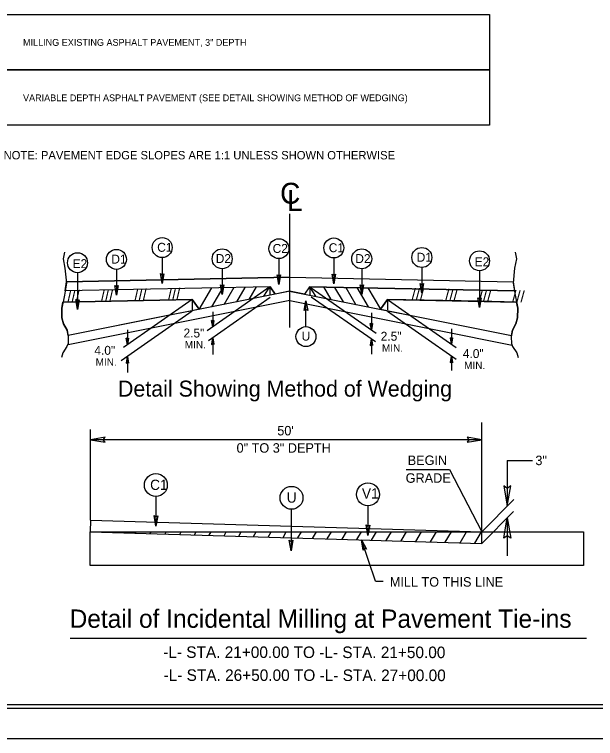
# Model space of a CAD drawing. Extents: x 1497225 to 1499181, y 579958 to 582278.
# Drawn here: x 1497449 to 1497879, y 581178 to 581713 of the extents above; entities that cross this region are included whole.
import ezdxf

# ---------------------------------------------------------------- set-up
doc = ezdxf.new("R2010")
doc.units = 0
for name, color, linetype in [('Default', 7, 'Continuous'), ('Old_Level_1', 7, 'Continuous'), ('Old_Level_11', 7, 'Continuous'), ('Old_Level_4', 7, 'Continuous'), ('Prop Dimension', 7, 'Continuous'), ('Prop Dimension Text', 7, 'Continuous'), ('Prop EOT', 7, 'Continuous'), ('Prop Pavement Schedule Description CELL', 7, 'Continuous'), ('Sheet Cutting Line CELL', 7, 'Continuous'), ('Sheet Plot Border Inside CELL', 7, 'Continuous'), ('Sheet Plot Border Outside CELL', 7, 'Continuous'), ('Sheet Typical CELL', 7, 'Continuous'), ('Typical Detail Wedge2 CELL', 7, 'Continuous'), ('Typical ID Circle CELL', 7, 'Continuous'), ('Typical Terminator CELL', 7, 'Continuous'), ('Typical Text Centerline CELL', 7, 'Continuous'), ('Typical Text General CELL', 7, 'Continuous'), ('Typical Text ID Circle CELL', 7, 'Continuous')]:
    doc.layers.add(name, color=color, linetype=linetype)

msp = doc.modelspace()

# ---------------------------------------------------------------- linework, layer by layer
at = {"layer": 'Default'}
for p, q in [((1497813.43, 581383.14), (1497813.43, 581349.46)), ((1497813.43, 581383.14), (1497832.03, 581383.14)), ((1497818.38, 581354.4), (1497794.6, 581330.63)), ((1497818.12, 581345.54), (1497794.6, 581322.03)), ((1497813.43, 581340.86), (1497813.43, 581312.76))]:
    msp.add_line(p, q, dxfattribs=at)
at = {"layer": 'Old_Level_1'}
for p, q in [((1497738.7, 581376.51), (1497770.88, 581376.51)), ((1497770.88, 581376.51), (1497794.6, 581330.63)), ((1497715.98, 581294.03), (1497705.67, 581324.67)), ((1497715.98, 581294.03), (1497721.85, 581294.03)), ((1497490.52, 581252), (1497871.88, 581252))]:
    msp.add_line(p, q, dxfattribs=at)
at = {"layer": 'Old_Level_11'}
for points in [[(1497516.3, 581400.45), (1497505.57, 581398.59), (1497516.37, 581396.67), (1497515, 581398.57)], [(1497783.88, 581396.71), (1497794.6, 581398.59), (1497783.79, 581400.48), (1497785.17, 581398.59)]]:
    msp.add_lwpolyline(points, close=True, dxfattribs=at)
at = {"layer": 'Prop Dimension'}
for p, q in [((1497794.6, 581330.63), (1497794.6, 581411.36)), ((1497505.57, 581339.22), (1497505.57, 581406.18)), ((1497794.6, 581398.59), (1497505.57, 581398.59))]:
    msp.add_line(p, q, dxfattribs=at)
msp.add_lwpolyline([(1497505.31, 581330.63), (1497869.71, 581330.63), (1497869.71, 581305.58), (1497505.31, 581305.58)], close=True, dxfattribs=at)
at = {"layer": 'Prop EOT'}
for p, q in [((1497505.57, 581339.22), (1497505.31, 581330.63)), ((1497505.57, 581339.22), (1497794.6, 581330.63)), ((1497505.31, 581330.63), (1497794.6, 581322.03)), ((1497506.1, 581330.6), (1497506.12, 581330.63)), ((1497517, 581330.28), (1497517.2, 581330.63)), ((1497527.9, 581329.96), (1497528.29, 581330.63)), ((1497538.8, 581329.63), (1497539.37, 581330.63)), ((1497549.69, 581329.31), (1497550.46, 581330.63)), ((1497560.59, 581328.98), (1497561.54, 581330.63)), ((1497571.49, 581328.66), (1497572.63, 581330.63)), ((1497582.39, 581328.34), (1497583.71, 581330.63)), ((1497593.29, 581328.01), (1497594.8, 581330.63)), ((1497604.18, 581327.69), (1497605.88, 581330.63)), ((1497615.08, 581327.37), (1497616.97, 581330.63)), ((1497625.98, 581327.04), (1497628.05, 581330.63)), ((1497636.88, 581326.72), (1497639.14, 581330.63)), ((1497647.78, 581326.39), (1497650.22, 581330.63)), ((1497658.68, 581326.07), (1497661.31, 581330.63)), ((1497669.57, 581325.75), (1497672.39, 581330.63)), ((1497680.47, 581325.42), (1497683.48, 581330.63)), ((1497691.37, 581325.1), (1497694.56, 581330.63)), ((1497702.27, 581324.77), (1497705.65, 581330.63)), ((1497713.17, 581324.45), (1497716.73, 581330.63)), ((1497724.06, 581324.13), (1497727.82, 581330.63)), ((1497734.96, 581323.8), (1497738.9, 581330.63)), ((1497745.86, 581323.48), (1497749.99, 581330.63)), ((1497756.76, 581323.15), (1497761.07, 581330.63)), ((1497767.66, 581322.83), (1497772.16, 581330.63)), ((1497778.55, 581322.51), (1497783.24, 581330.63)), ((1497789.45, 581322.18), (1497794.33, 581330.63)), ((1497794.6, 581322.03), (1497794.6, 581330.63))]:
    msp.add_line(p, q, dxfattribs=at)
at = {"layer": 'Prop Pavement Schedule Description CELL'}
for points in [[(1497441.11, 581671.59), (1497400.21, 581671.59), (1497400.21, 581712.5), (1497800.21, 581712.5), (1497800.21, 581671.59), (1497441.11, 581671.59), (1497441.11, 581712.5)], [(1497441.11, 581630.68), (1497400.21, 581630.68), (1497400.21, 581671.59), (1497800.21, 581671.59), (1497800.21, 581630.68), (1497441.11, 581630.68), (1497441.11, 581671.59)]]:
    msp.add_lwpolyline(points, dxfattribs=at)
at = {"layer": 'Sheet Cutting Line CELL'}
msp.add_line((1497225.23, 581177.96), (1498909.23, 581177.96), dxfattribs=at)
at = {"layer": 'Sheet Plot Border Inside CELL'}
msp.add_lwpolyline([(1498904.73, 582255.51), (1497238.23, 582255.51), (1497238.23, 581200.41), (1498904.73, 581200.41)], close=True, dxfattribs=at)
at = {"layer": 'Sheet Plot Border Outside CELL'}
msp.add_lwpolyline([(1498909.23, 582277.96), (1497225.23, 582277.96), (1497225.23, 581177.96), (1498909.23, 581177.96)], close=True, dxfattribs=at)
at = {"layer": 'Sheet Typical CELL'}
msp.add_lwpolyline([(1498892.23, 582252.96), (1497392.23, 582252.96), (1497392.23, 581202.96), (1498892.23, 581202.96)], close=True, dxfattribs=at)
at = {"layer": 'Typical Detail Wedge2 CELL'}
for p, q in [((1497652.78, 581481.31), (1497652.78, 581565.38)), ((1497652.78, 581481.31), (1497652.78, 581538.73)), ((1497486.83, 581508.52), (1497487.77, 581515.15)), ((1497652.77, 581518.45), (1497487.77, 581515.15)), ((1497487.77, 581515.15), (1497652.77, 581518.45)), ((1497652.77, 581518.45), (1497817.78, 581515.15)), ((1497652.79, 581518.45), (1497817.78, 581515.15)), ((1497817.78, 581515.15), (1497818.73, 581508.52)), ((1497638.3, 581511.55), (1497486.83, 581508.52)), ((1497638.3, 581511.55), (1497486.83, 581508.52)), ((1497595.03, 581510.68), (1497585.65, 581494.62)), ((1497638.11, 581511.43), (1497591.62, 581478.87)), ((1497603.26, 581510.85), (1497594.96, 581496.61)), ((1497611.41, 581511.01), (1497603.96, 581498.24)), ((1497619.62, 581510.99), (1497613.45, 581500.42)), ((1497627.9, 581511.42), (1497622.52, 581502.19)), ((1497633.61, 581504.5), (1497638.09, 581511.49)), ((1497638.09, 581511.49), (1497638.09, 581505.74)), ((1497642.01, 581506.12), (1497638.3, 581511.55)), ((1497638.3, 581511.38), (1497642.01, 581506.12)), ((1497667.37, 581511.55), (1497663.55, 581506.12)), ((1497667.37, 581511.55), (1497663.55, 581506.12)), ((1497667.13, 581511.43), (1497667.37, 581511.42)), ((1497667.37, 581511.55), (1497818.73, 581508.52)), ((1497818.73, 581508.52), (1497667.37, 581511.55)), ((1497671.95, 581504.5), (1497667.47, 581511.49)), ((1497667.47, 581511.49), (1497667.47, 581505.16)), ((1497668.63, 581510.67), (1497716.53, 581477.13)), ((1497677.65, 581511.42), (1497683.04, 581502.19)), ((1497685.93, 581510.99), (1497692.1, 581500.42)), ((1497694.14, 581511.01), (1497701.6, 581498.24)), ((1497702.29, 581510.85), (1497710.6, 581496.61)), ((1497710.54, 581510.68), (1497719.77, 581494.85)), ((1497653.02, 581508.31), (1497489.01, 581475.5)), ((1497638.22, 581503.47), (1497592.73, 581471.62)), ((1497652.53, 581508.31), (1497642.01, 581506.12)), ((1497652.53, 581508.31), (1497816.55, 581475.5)), ((1497663.55, 581506.12), (1497652.53, 581508.31)), ((1497668.57, 581504.15), (1497716, 581470.95)), ((1497580.59, 581502.13), (1497485.23, 581500.21)), ((1497485.23, 581500.21), (1497580.59, 581502.13)), ((1497652.71, 581501.25), (1497488.96, 581468.49)), ((1497580.59, 581502.13), (1497529.96, 581466.66)), ((1497585.78, 581494.83), (1497580.59, 581502.13)), ((1497580.59, 581502.13), (1497580.59, 581493.8)), ((1497580.59, 581502.13), (1497585.77, 581494.85)), ((1497652.84, 581501.25), (1497816.98, 581468.41)), ((1497724.96, 581502.13), (1497719.77, 581494.85)), ((1497719.78, 581494.85), (1497724.96, 581502.13)), ((1497724.96, 581502.13), (1497820.33, 581500.21)), ((1497724.96, 581502.13), (1497724.96, 581494.39)), ((1497792.97, 581500.76), (1497724.96, 581502.13)), ((1497725.73, 581501.59), (1497775.67, 581466.61)), ((1497820.33, 581500.21), (1497792.97, 581500.76)), ((1497580.55, 581493.54), (1497528.2, 581456.7)), ((1497580.59, 581493.81), (1497563.99, 581490.49)), ((1497585.77, 581494.85), (1497580.59, 581493.81)), ((1497595.86, 581492.9), (1497595.86, 581481.84)), ((1497719.77, 581494.85), (1497741.57, 581490.49)), ((1497724.96, 581493.38), (1497775.59, 581457.92)), ((1497563.99, 581490.49), (1497489.01, 581475.5)), ((1497713.03, 581492.26), (1497713.03, 581479.58)), ((1497741.57, 581490.49), (1497816.55, 581475.5)), ((1497595.86, 581481.84), (1497595, 581486.69)), ((1497595.86, 581486.06), (1497595, 581486.69)), ((1497595.86, 581481.84), (1497595.12, 581486.6)), ((1497595.24, 581486.51), (1497595.86, 581481.84)), ((1497595.86, 581481.84), (1497595.36, 581486.42)), ((1497595.49, 581486.33), (1497595.86, 581481.84)), ((1497595.86, 581481.84), (1497595.61, 581486.24)), ((1497595.73, 581486.15), (1497595.86, 581481.84)), ((1497595.86, 581481.84), (1497596.72, 581486.69)), ((1497596.72, 581486.69), (1497595.86, 581486.06)), ((1497596.6, 581486.6), (1497595.86, 581481.84)), ((1497595.86, 581481.84), (1497596.46, 581486.51)), ((1497596.34, 581486.42), (1497595.86, 581481.84)), ((1497595.86, 581481.84), (1497596.22, 581486.33)), ((1497596.1, 581486.24), (1497595.86, 581481.84)), ((1497595.86, 581481.84), (1497595.98, 581486.15)), ((1497595.86, 581486.06), (1497595.86, 581481.84)), ((1497713.03, 581479.58), (1497712.18, 581484.44)), ((1497713.03, 581483.81), (1497712.18, 581484.44)), ((1497713.03, 581479.58), (1497712.3, 581484.35)), ((1497712.42, 581484.26), (1497713.03, 581479.58)), ((1497713.03, 581479.58), (1497712.54, 581484.16)), ((1497712.66, 581484.07), (1497713.03, 581479.58)), ((1497713.03, 581479.58), (1497712.78, 581483.99)), ((1497712.9, 581483.9), (1497713.03, 581479.58)), ((1497713.03, 581479.58), (1497713.89, 581484.44)), ((1497713.89, 581484.44), (1497713.03, 581483.81)), ((1497713.76, 581484.35), (1497713.03, 581479.58)), ((1497713.03, 581479.58), (1497713.64, 581484.26)), ((1497713.52, 581484.16), (1497713.03, 581479.58)), ((1497713.03, 581479.58), (1497713.4, 581484.07)), ((1497713.27, 581483.99), (1497713.03, 581479.58)), ((1497713.03, 581479.58), (1497713.15, 581483.9)), ((1497713.03, 581483.81), (1497713.03, 581479.58)), ((1497532.81, 581479.68), (1497532.81, 581468.65)), ((1497772.24, 581480.48), (1497772.24, 581469.02)), ((1497532.81, 581468.65), (1497531.95, 581473.51)), ((1497532.81, 581472.88), (1497531.95, 581473.51)), ((1497532.81, 581468.65), (1497532.07, 581473.42)), ((1497532.2, 581473.32), (1497532.81, 581468.65)), ((1497532.81, 581468.65), (1497532.32, 581473.24)), ((1497532.44, 581473.15), (1497532.81, 581468.65)), ((1497532.81, 581468.65), (1497532.56, 581473.06)), ((1497532.69, 581472.97), (1497532.81, 581468.65)), ((1497532.81, 581468.65), (1497533.66, 581473.51)), ((1497533.66, 581473.51), (1497532.81, 581472.88)), ((1497533.54, 581473.42), (1497532.81, 581468.65)), ((1497532.81, 581468.65), (1497533.42, 581473.32)), ((1497533.3, 581473.24), (1497532.81, 581468.65)), ((1497532.81, 581468.65), (1497533.17, 581473.15)), ((1497533.06, 581473.06), (1497532.81, 581468.65)), ((1497532.81, 581468.65), (1497532.93, 581472.97)), ((1497532.81, 581472.88), (1497532.81, 581468.65)), ((1497595.86, 581473.81), (1497595, 581468.96)), ((1497595.12, 581469.05), (1497595.86, 581473.81)), ((1497595.86, 581473.81), (1497595.24, 581469.14)), ((1497595.36, 581469.24), (1497595.86, 581473.81)), ((1497595.86, 581473.81), (1497595.49, 581469.32)), ((1497595.61, 581469.41), (1497595.86, 581473.81)), ((1497595.86, 581473.81), (1497595.73, 581469.5)), ((1497595.86, 581473.81), (1497595.86, 581461.36)), ((1497595.86, 581473.81), (1497596.72, 581468.96)), ((1497595.86, 581469.59), (1497595.86, 581473.81)), ((1497595.98, 581469.5), (1497595.86, 581473.81)), ((1497595.86, 581473.81), (1497596.1, 581469.41)), ((1497596.22, 581469.32), (1497595.86, 581473.81)), ((1497595.86, 581473.81), (1497596.34, 581469.24)), ((1497596.46, 581469.14), (1497595.86, 581473.81)), ((1497595.86, 581473.81), (1497596.6, 581469.05)), ((1497713.03, 581473.02), (1497712.18, 581468.17)), ((1497712.3, 581468.27), (1497713.03, 581473.02)), ((1497713.03, 581473.02), (1497712.42, 581468.35)), ((1497712.54, 581468.45), (1497713.03, 581473.02)), ((1497713.03, 581473.02), (1497712.66, 581468.53)), ((1497712.78, 581468.62), (1497713.03, 581473.02)), ((1497713.03, 581473.02), (1497712.9, 581468.71)), ((1497713.03, 581473.02), (1497713.03, 581461.68)), ((1497713.03, 581473.02), (1497713.89, 581468.17)), ((1497713.03, 581468.8), (1497713.03, 581473.02)), ((1497713.15, 581468.71), (1497713.03, 581473.02)), ((1497713.03, 581473.02), (1497713.27, 581468.62)), ((1497713.4, 581468.53), (1497713.03, 581473.02)), ((1497713.03, 581473.02), (1497713.52, 581468.45)), ((1497713.64, 581468.35), (1497713.03, 581473.02)), ((1497713.03, 581473.02), (1497713.76, 581468.27)), ((1497772.24, 581469.02), (1497771.39, 581473.86)), ((1497772.24, 581473.24), (1497771.39, 581473.86)), ((1497772.24, 581469.02), (1497771.51, 581473.77)), ((1497771.63, 581473.69), (1497772.24, 581469.02)), ((1497772.24, 581469.02), (1497771.75, 581473.6)), ((1497771.87, 581473.51), (1497772.24, 581469.02)), ((1497772.24, 581469.02), (1497771.99, 581473.42)), ((1497772.11, 581473.32), (1497772.24, 581469.02)), ((1497772.24, 581469.02), (1497773.1, 581473.86)), ((1497773.1, 581473.86), (1497772.24, 581473.24)), ((1497772.97, 581473.77), (1497772.24, 581469.02)), ((1497772.24, 581469.02), (1497772.85, 581473.69)), ((1497772.73, 581473.6), (1497772.24, 581469.02)), ((1497772.24, 581469.02), (1497772.6, 581473.51)), ((1497772.48, 581473.42), (1497772.24, 581469.02)), ((1497772.24, 581469.02), (1497772.36, 581473.32)), ((1497772.24, 581473.24), (1497772.24, 581469.02)), ((1497595, 581468.96), (1497595.86, 581469.59)), ((1497595.86, 581469.59), (1497596.72, 581468.96)), ((1497712.18, 581468.17), (1497713.03, 581468.8)), ((1497713.03, 581468.8), (1497713.89, 581468.17)), ((1497772.24, 581460.27), (1497771.39, 581455.42)), ((1497771.51, 581455.51), (1497772.24, 581460.27)), ((1497772.24, 581460.27), (1497771.63, 581455.6)), ((1497771.75, 581455.69), (1497772.24, 581460.27)), ((1497772.24, 581460.27), (1497771.87, 581455.78)), ((1497771.99, 581455.87), (1497772.24, 581460.27)), ((1497772.24, 581460.27), (1497772.11, 581455.96)), ((1497772.24, 581460.27), (1497772.24, 581449.62)), ((1497772.24, 581460.27), (1497773.1, 581455.42)), ((1497772.24, 581456.05), (1497772.24, 581460.27)), ((1497772.36, 581455.96), (1497772.24, 581460.27)), ((1497772.24, 581460.27), (1497772.48, 581455.87)), ((1497772.6, 581455.78), (1497772.24, 581460.27)), ((1497772.24, 581460.27), (1497772.73, 581455.69)), ((1497772.85, 581455.6), (1497772.24, 581460.27)), ((1497772.24, 581460.27), (1497772.97, 581455.51)), ((1497532.81, 581459.93), (1497531.95, 581455.08)), ((1497531.95, 581455.08), (1497532.81, 581455.71)), ((1497532.08, 581455.17), (1497532.81, 581459.93)), ((1497532.81, 581459.93), (1497532.2, 581455.26)), ((1497532.32, 581455.35), (1497532.81, 581459.93)), ((1497532.81, 581459.93), (1497532.44, 581455.44)), ((1497532.56, 581455.53), (1497532.81, 581459.93)), ((1497532.81, 581459.93), (1497532.69, 581455.61)), ((1497532.81, 581459.93), (1497532.81, 581448.14)), ((1497532.81, 581459.93), (1497533.66, 581455.08)), ((1497532.81, 581455.71), (1497532.81, 581459.93)), ((1497532.93, 581455.61), (1497532.81, 581459.93)), ((1497532.81, 581459.93), (1497533.06, 581455.53)), ((1497533.18, 581455.44), (1497532.81, 581459.93)), ((1497532.81, 581459.93), (1497533.3, 581455.35)), ((1497533.42, 581455.26), (1497532.81, 581459.93)), ((1497532.81, 581459.93), (1497533.54, 581455.17)), ((1497532.81, 581455.71), (1497533.66, 581455.08)), ((1497771.39, 581455.42), (1497772.24, 581456.05)), ((1497772.24, 581456.05), (1497773.1, 581455.42))]:
    msp.add_line(p, q, dxfattribs=at)
for points in [[(1497486.24, 581536.93), (1497485.36, 581532.1), (1497486.68, 581525.22), (1497487.85, 581514.1), (1497486.24, 581505.32), (1497484.34, 581495.8), (1497484.49, 581488.63), (1497485.66, 581484.1), (1497488.3, 581479.55), (1497489.17, 581474.58), (1497489.02, 581469.61), (1497488.14, 581467.26), (1497485.07, 581462.58), (1497484.05, 581459.35)], [(1497819.31, 581536.93), (1497820.19, 581532.1), (1497818.88, 581525.22), (1497817.7, 581514.1), (1497819.31, 581505.32), (1497821.22, 581495.8), (1497821.07, 581488.63), (1497819.89, 581484.1), (1497817.26, 581479.55), (1497816.39, 581474.58), (1497816.53, 581469.61), (1497817.41, 581467.26), (1497820.48, 581462.58), (1497821.5, 581459.35)], [(1497489.01, 581475.5), (1497488.3, 581479.55), (1497485.66, 581484.1), (1497484.49, 581488.63), (1497484.34, 581495.8), (1497485.22, 581500.21)], [(1497816.55, 581475.5), (1497817.26, 581479.55), (1497819.89, 581484.1), (1497821.07, 581488.63), (1497821.22, 581495.8), (1497820.33, 581500.21)]]:
    msp.add_lwpolyline(points, dxfattribs=at)
at = {"layer": 'Typical ID Circle CELL'}
for p, q in [((1497558.51, 581533.05), (1497558.51, 581514)), ((1497644.76, 581532.23), (1497644.76, 581513.18)), ((1497685.28, 581532.75), (1497685.28, 581513.7)), ((1497602.82, 581524.77), (1497602.82, 581505.72)), ((1497705.92, 581524.73), (1497705.92, 581505.68)), ((1497750.32, 581525.72), (1497750.32, 581506.67)), ((1497495.93, 581521.87), (1497495.93, 581494.79)), ((1497524.71, 581524.34), (1497524.71, 581505.3)), ((1497792.97, 581523.29), (1497792.97, 581496.21)), ((1497664.72, 581482.03), (1497664.72, 581501.08)), ((1497553.85, 581356.59), (1497553.85, 581334.72)), ((1497710.51, 581349.7), (1497710.51, 581327.83)), ((1497653.79, 581347.2), (1497653.79, 581316.64))]:
    msp.add_line(p, q, dxfattribs=at)
for centre, radius in [((1497558.51, 581540.41), 7.37), ((1497644.76, 581539.6), 7.37), ((1497685.28, 581540.12), 7.37), ((1497750.32, 581533.08), 7.37), ((1497495.93, 581529.24), 7.37), ((1497524.71, 581531.71), 7.37), ((1497602.82, 581532.13), 7.37), ((1497705.92, 581532.1), 7.37), ((1497792.97, 581530.66), 7.37), ((1497664.72, 581474.67), 7.37), ((1497553.85, 581365.05), 8.46), ((1497654.06, 581355.66), 8.46), ((1497710.51, 581358.16), 8.46)]:
    msp.add_circle(centre, radius, dxfattribs=at)
at = {"layer": 'Typical Terminator CELL'}
for points in [[(1497559.74, 581521.14), (1497558.51, 581514), (1497557.24, 581521.18), (1497558.51, 581520.27)], [(1497559.74, 581521.14), (1497558.51, 581514), (1497557.24, 581521.18), (1497558.51, 581520.27)], [(1497645.99, 581520.33), (1497644.76, 581513.18), (1497643.49, 581520.37), (1497644.76, 581519.46)], [(1497645.99, 581520.33), (1497644.76, 581513.18), (1497643.49, 581520.37), (1497644.76, 581519.46)], [(1497686.51, 581520.85), (1497685.28, 581513.7), (1497684.01, 581520.89), (1497685.28, 581519.98)], [(1497686.51, 581520.85), (1497685.28, 581513.7), (1497684.01, 581520.89), (1497685.28, 581519.98)], [(1497751.55, 581513.81), (1497750.32, 581506.67), (1497749.05, 581513.85), (1497750.32, 581512.94)], [(1497751.55, 581513.81), (1497750.32, 581506.67), (1497749.05, 581513.85), (1497750.32, 581512.94)], [(1497525.94, 581512.44), (1497524.71, 581505.3), (1497523.44, 581512.48), (1497524.71, 581511.57)], [(1497525.94, 581512.44), (1497524.71, 581505.3), (1497523.44, 581512.48), (1497524.71, 581511.57)], [(1497604.05, 581512.87), (1497602.82, 581505.72), (1497601.55, 581512.91), (1497602.82, 581511.99)], [(1497604.05, 581512.87), (1497602.82, 581505.72), (1497601.55, 581512.91), (1497602.82, 581511.99)], [(1497707.15, 581512.83), (1497705.92, 581505.68), (1497704.65, 581512.87), (1497705.92, 581511.95)], [(1497707.15, 581512.83), (1497705.92, 581505.68), (1497704.65, 581512.87), (1497705.92, 581511.95)], [(1497794.2, 581503.36), (1497792.97, 581496.21), (1497791.7, 581503.4), (1497792.97, 581502.48)], [(1497497.16, 581501.93), (1497495.93, 581494.79), (1497494.66, 581501.97), (1497495.93, 581501.06)], [(1497663.49, 581493.94), (1497664.72, 581501.08), (1497665.99, 581493.9), (1497664.72, 581494.81)], [(1497663.49, 581493.94), (1497664.72, 581501.08), (1497665.99, 581493.9), (1497664.72, 581494.81)], [(1497810.85, 581364.45), (1497813.43, 581349.46), (1497816.1, 581364.54), (1497813.43, 581362.62)], [(1497555.18, 581342.45), (1497553.85, 581334.72), (1497552.47, 581342.5), (1497553.85, 581341.51)], [(1497810.85, 581325.86), (1497813.43, 581340.86), (1497816.1, 581325.78), (1497813.43, 581327.69)], [(1497711.84, 581335.56), (1497710.51, 581327.83), (1497709.13, 581335.61), (1497710.51, 581334.62)], [(1497655.12, 581324.37), (1497653.79, 581316.64), (1497652.41, 581324.41), (1497653.79, 581323.42)], [(1497706.87, 581316.92), (1497705.67, 581324.67), (1497709.45, 581317.74), (1497707.83, 581318.24)]]:
    msp.add_lwpolyline(points, close=True, dxfattribs=at)

# ---------------------------------------------------------------- texts
at = {"layer": 'Old_Level_1'}
for s, p in [('3"', (1497834.21, 581379.79)), ('MILL TO THIS LINE', (1497726.66, 581290.09))]:
    msp.add_text(s, height=7, dxfattribs=at).set_placement(p)
for s, p in [('-L- STA. 21+00.00 TO -L- STA. 21+50.00', (1497559.23, 581237.49)), ('-L- STA. 26+50.00 TO -L- STA. 27+00.00', (1497559.5, 581220.54))]:
    msp.add_text(s, height=8.5, rotation=359.9492, dxfattribs=at).set_placement(p)
at = {"layer": 'Old_Level_4'}
msp.add_text('NOTE: PAVEMENT EDGE SLOPES ARE 1:1 UNLESS SHOWN OTHERWISE', height=6.1875, rotation=360, dxfattribs=at).set_placement((1497441.36, 581605.52))
at = {"layer": 'Prop Dimension Text'}
for s, p in [("50'", (1497643.53, 581401.74)), ('0" TO 3" DEPTH', (1497613.47, 581388.97))]:
    msp.add_text(s, height=7, dxfattribs=at).set_placement(p)
for s, p in [('BEGIN', (1497739.9, 581379.89)), ('GRADE', (1497738.39, 581366.77))]:
    msp.add_text(s, height=7, rotation=0.0001, dxfattribs=at).set_placement(p)
at = {"layer": 'Prop Pavement Schedule Description CELL'}
for s, p in [('MILLING EXISTING ASPHALT PAVEMENT, 3" DEPTH', (1497455.7, 581689.37)), ('VARIABLE DEPTH ASPHALT PAVEMENT (SEE DETAIL SHOWING METHOD OF WEDGING)', (1497455.7, 581648.47))]:
    msp.add_text(s, height=5, dxfattribs=at).set_placement(p)
at = {"layer": 'Typical Detail Wedge2 CELL'}
for height, rotation, p in [(8.274, 1.1447, (1497488.51, 581500.33)), (8.275, 1.1464, (1497513.24, 581500.62)), (8.271, 1.1445, (1497538.02, 581501.35)), (8.272, 1.1463, (1497562.83, 581501.86)), (8.272, 358.8553, (1497742.72, 581501.86)), (8.271, 358.8536, (1497767.53, 581501.35)), (8.275, 358.8554, (1497792.31, 581500.62)), (8.274, 358.8537, (1497817.04, 581500.33))]:
    msp.add_text('/// ', height=height, rotation=rotation, dxfattribs=at).set_placement(p)
for s, height, p in [('2.5"', 6.597, (1497574.25, 581474.04)), ('2.5"', 6.597, (1497719.94, 581471.64)), ('MIN.', 5.512, (1497575.22, 581465.93)), ('4.0"', 6.597, (1497508.4, 581461.26)), ('MIN.', 5.512, (1497720.9, 581463.53)), ('4.0"', 6.597, (1497780.61, 581458.86)), ('MIN.', 5.512, (1497509.36, 581453.15)), ('MIN.', 5.512, (1497781.58, 581450.75))]:
    msp.add_text(s, height=height, dxfattribs=at).set_placement(p)
at = {"layer": 'Typical Text Centerline CELL'}
for s, height, rotation, p in [('C', 15.47, 360, (1497645.64, 581572.78)), ('L', 15.48, 359.9469, (1497650.79, 581567.5))]:
    msp.add_text(s, height=height, rotation=rotation, dxfattribs=at).set_placement(p)
at = {"layer": 'Typical Text General CELL'}
for s, height, p in [('Detail Showing Method of Wedging', 11.8167, (1497525.84, 581430.36)), ('Detail of Incidental Milling at Pavement Tie-ins', 13.52, (1497490.14, 581259.69))]:
    msp.add_text(s, height=height, dxfattribs=at).set_placement(p)
at = {"layer": 'Typical Text ID Circle CELL'}
for s, height, p in [('C1', 6.597, (1497554.82, 581537.3)), ('C2', 6.597, (1497640.12, 581536.48)), ('C1', 6.597, (1497681.58, 581537.01)), ('D1', 6.597, (1497520.92, 581528.6)), ('D2', 6.597, (1497598.08, 581529.02)), ('D2', 6.597, (1497701.18, 581528.98)), ('D1', 6.597, (1497746.53, 581529.97)), ('E2', 6.597, (1497492.35, 581525.23)), ('E2', 6.597, (1497789.39, 581526.65)), ('U', 6.6, (1497661.5, 581471.75)), ('C1', 7.575, (1497549.6, 581361.48)), ('U', 7.58, (1497650.5, 581352.09)), ('V1', 7.575, (1497706.06, 581355.13))]:
    msp.add_text(s, height=height, dxfattribs=at).set_placement(p)

doc.saveas('drawing.dxf')
